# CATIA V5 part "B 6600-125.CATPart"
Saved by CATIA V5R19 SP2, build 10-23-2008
Part number: B 6600-125
Bounding box of the stored display mesh (mm): x -59.975 to 59.975, y -59.975 to 59.975, z 0 to 390
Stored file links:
  C:\Users\Bora\Desktop\3D Katı model\B serisi\B 6600\B 6600-125.CATPart
  C:\Program Files\Dassault Systemes\B19\intel_a\reffiles\standard\MetricThickPitch.txt
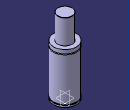
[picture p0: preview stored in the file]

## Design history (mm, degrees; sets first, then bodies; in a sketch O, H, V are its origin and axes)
Body1 (main body)
  Sketch1 on yz-plane, origin (0, 0, 0), H (0, 1, 0), V (0, 0, 1)
    point P3 (37.5, 389)
    point P5 (37.5, 389)
    point P10 (60, 237)
    point P11 (60, 242)
    point P13 (60, 242)
    point P14 (60, 237)
    line L1 (60, 0) -> (60, 8)
    line L2 (37.5, 389) -> (37.5, 262)
    arc A1 centre (36.5, 389) radius 1 from (37.5, 389) to (36.5, 390) ccw
    line L3 (56, 13) -> (56, 8)
    line L4 (60, 13) -> (60, 237)
    line L5 (60, 242) -> (60, 262)
    arc A2 centre (60, 239.5) radius 2.5 from (60, 242) to (60, 237) ccw
    line L6 (36.5, 390) -> (0, 390)
    point P15 (0, 390)
    line L7 (37.5, 262) -> (60, 262)
    line L8 (0, 0) -> (60, 0)
    line L9 (56, 13) -> (60, 13)
    line L10 (56, 8) -> (60, 8)
    coincidence: P15 V, P3 P5, P10 P14, P11 P13
    tangency: L6 A1
    horizontal: L7 H, L8 H, L9 H, L10 H
  Shaft1: profile Sketch1, axis Sketch1.V, angle 360
  Sketch2 on face of Shaft1 from Sketch1.L8, origin (0, 0, 0), H (1, 0, 0), V (0, -1, 0)
    point P1 (40, 0)
    distance P1 V = 40
  Hole1: placed by Sketch2, at (40, 0, 0) direction (0, 0, 1), diameter 8.376, depth 16, threaded "M10", thread diameter 10, thread depth 16, pitch 1.5
  CircPattern1: of Hole1, instances 4, angular step 90, axis from xy-plane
